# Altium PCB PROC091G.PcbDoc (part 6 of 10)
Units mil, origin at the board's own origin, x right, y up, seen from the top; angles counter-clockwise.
Board outline 4538.11 x 994.94 mil, 8 copper layers (Top Layer, GND1, Sig1, PWR1, PWR2, Sig2, GND2, Bottom Layer), stack 59.155 mil thick; 446 components, 329 nets, 5050 pads, 868 vias.
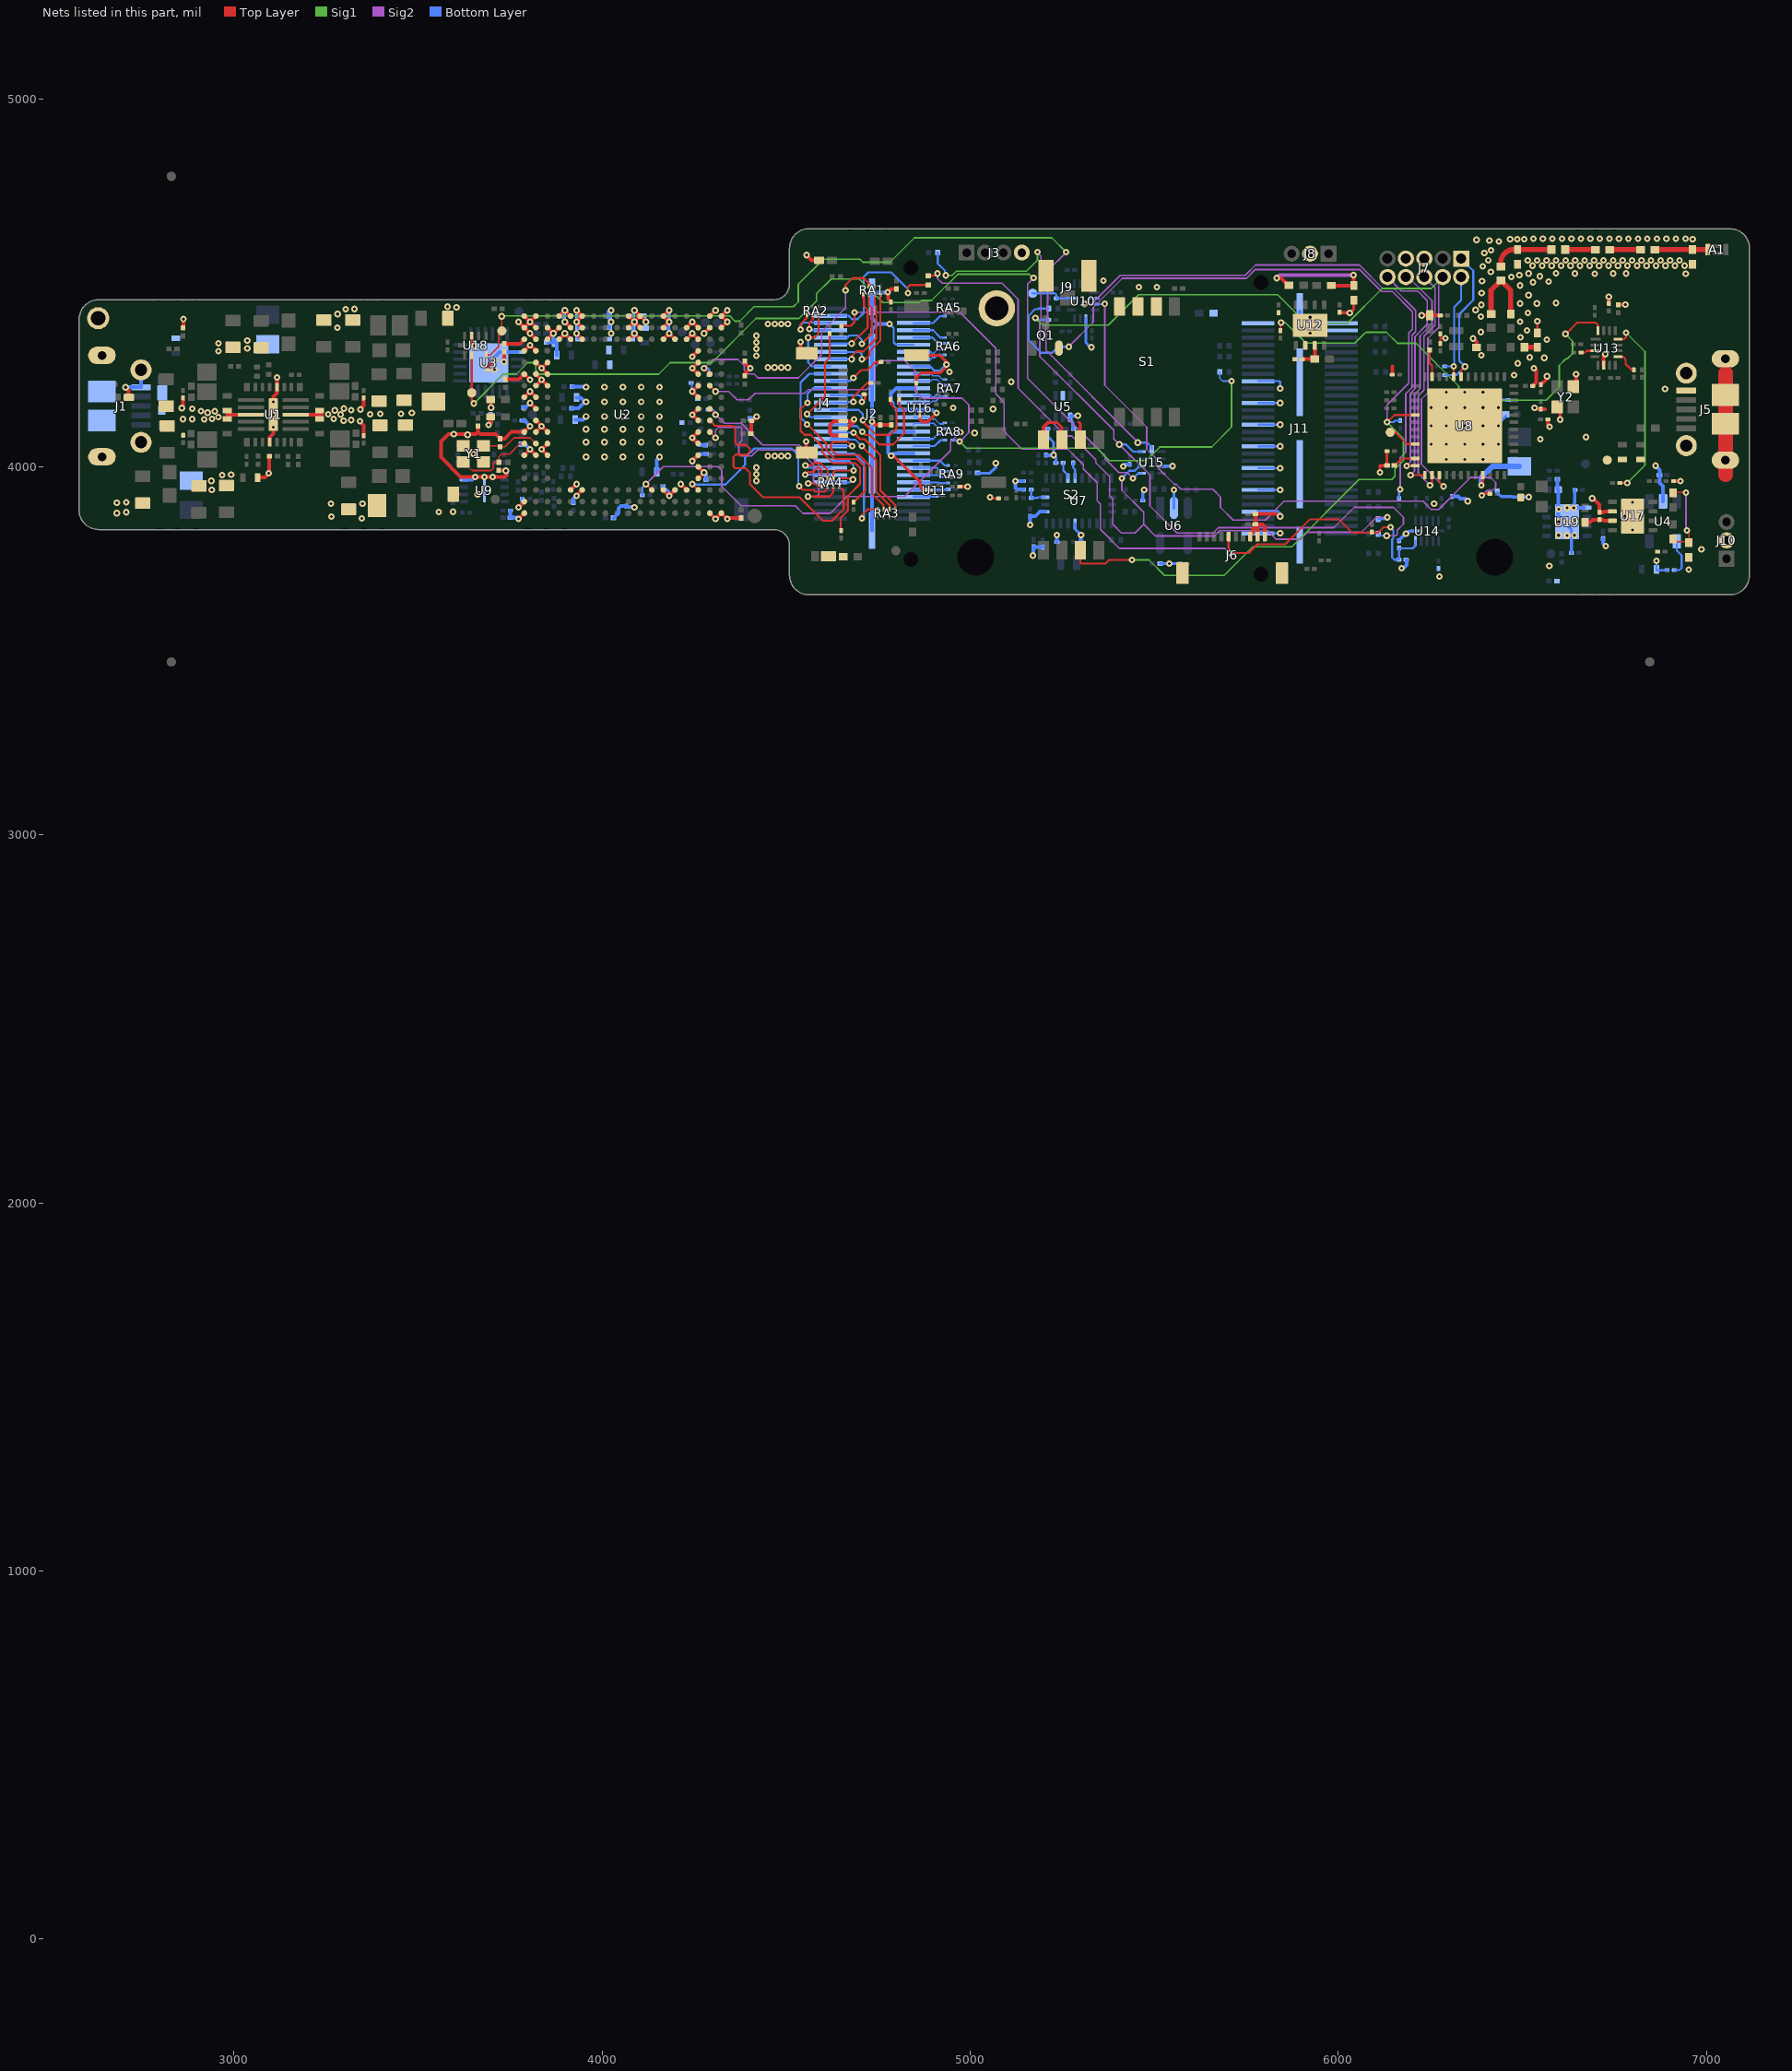
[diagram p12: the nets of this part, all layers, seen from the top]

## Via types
v1: diameter 18, hole 8, Top Layer to Bottom Layer, tented both sides, 832 vias
v2: diameter 19.68, hole 7.87, Top Layer to Bottom Layer, tented both sides, 34 vias
v3: diameter 17, hole 7.87, Top Layer to Bottom Layer, tented both sides, 1 vias
v4: diameter 17, hole 8, Top Layer to Bottom Layer, tented both sides, 1 vias

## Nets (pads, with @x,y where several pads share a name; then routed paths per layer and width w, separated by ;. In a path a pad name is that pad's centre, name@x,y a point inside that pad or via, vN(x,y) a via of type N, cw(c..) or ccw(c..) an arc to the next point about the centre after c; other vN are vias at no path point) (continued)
AR_SYNC_IN: R157.1 RA8.8 U2.U12 | length 1975
  Top Layer w5.5: U2.U12@4292.7,4220.35 v1(4308.45,4204.6)
  Sig1 w4.2: v1(4971.61,4068.25) 4989.78,4050.08 5344.37,4050.08 5377.44,4017.01 5478.18,4017.01 5514.94,4053.77 5656.33,4053.77 5710.24,4107.68 v1(5710.24,4232.45)
  Sig2 w4.2: v1(4308.45,4204.6) 4344.14,4204.6 4367.21,4181.54 4397.56,4181.54 4415.59,4199.56 4550.34,4199.56 4560.42,4209.65 4718.86,4209.65 4741.87,4232.66 4741.87,4271.44 4759.12,4288.69 4822.4,4288.69 4850.94,4260.15 4850.94,4204.65 4869.22,4186.37 4978,4186.37 4996.41,4167.96 4996.41,4093.05 v1(4971.61,4068.25)
  Bottom Layer w4.2: R157.1@5678.13,4257.72 5678.13,4240.18 5685.85,4232.45 v1(5710.24,4232.45)
  Bottom Layer w5.5: RA8.8@4952.69,4072.25 4967.61,4072.25 v1(4971.61,4068.25)
AR_SYNC_OUT_SOP1: R84.1 RA8.7 U2.M3 | length 1135.8
  Top Layer w5.5: v1(4119.47,3952.63) U2.M3@4135.22,3936.89
  Sig2 w4.2: v1(4119.47,3952.63) 4167.16,4000.33 4313.89,4000.33 4325.09,3989.12 4325.09,3946.41 4377.92,3893.59 4525.16,3893.59 4545.46,3873.29 4620.23,3873.29 4665.56,3918.63 4821.98,3918.63 4947.18,4043.83 4947.18,4067.33 v1(4973.31,4093.46)
  Bottom Layer w5.5: R84.1@4109.37,3922.4 4109.37,3942.53 v1(4119.47,3952.63) ; RA8.7@4952.69,4088 4967.85,4088 v1(4973.31,4093.46)
AR_TCK: RA4.2 U2.T3 | length 552.9
  Top Layer w5.5: v1(4245.46,3952.63) U2.T3@4261.2,3936.89 ; v1@4532.81,3949.39 v1(4535.35,3946.85) 4544.91,3937.29 4573.76,3937.29 4579.07,3931.99 4604.64,3931.99 4612.69,3940.04 RA4.2@4612.69,3946.67
  Bottom Layer w5.5: v1(4245.46,3952.63) 4246.46,3951.63 4335.33,3951.63 4388.35,4004.65 4388.35,4024.15 4414.2,4050 4514.75,4050 4532.92,4031.83 4532.92,3949.29 v1(4535.35,3946.85)
AR_TDI: RA4.4 U2.U9 | length 705.9
  Top Layer w5.5: U2.U9@4292.7,4125.86 4307.32,4111.24 4353.47,4111.24 4361.57,4103.14 4361.57,4065.53 4367.7,4059.39 4391,4059.39 4401.46,4048.93 4401.46,4040.6 4393.56,4032.7 4363.3,4032.7 4357.05,4026.45 4357.05,4000.45 4361.5,3996 4389.59,3996 4401.46,3984.13 4401.46,3952.48 4437.05,3916.9 4536.15,3916.9 4599.89,3853.17 4624.33,3853.17 4656.39,3885.22 4656.39,3934.47 RA4.4@4644.19,3946.67
AR_TDO_SOP0: R83.1 RA4.3 U2.U10 | length 591.7
  Top Layer w5.5: U2.U10@4292.7,4157.36 v1(4308.45,4141.61) ; v1(4559.05,3919.14) 4617.44,3919.14 4628.44,3930.13 RA4.3@4628.44,3946.67
  Sig2 w4.2: v1(4308.45,4141.61) 4332.17,4117.89 4378.11,4117.89 4436.42,4059.59 4535.55,4059.59 4588.41,4006.72 4588.41,3924.98 4582.57,3919.14 v1(4559.05,3919.14)
  Bottom Layer w4.2: R83.1@4288.32,4155.3 4301.27,4155.3 4308.45,4148.13 v1(4308.45,4141.61)
AR_TMS: RA4.1 U2.U8 | length 524.5
  Top Layer w5.5: U2.U8@4292.7,4094.37 v1(4308.45,4078.62) ; v1(4559.88,3955.04) 4577.77,3955.04 4586.24,3946.57 4596.85,3946.57 RA4.1@4596.94,3946.67
  Sig2 w4.2: v1(4308.45,4078.62) 4308.45,4099.58 4316.49,4107.62 4376.5,4107.62 4379.39,4104.74 4379.39,4070.75 ; 4379.05,4070.75 4371.62,4063.31 4371.62,4034.19 4376.26,4029.55 4406,4029.55 4422.02,4045.57 4533.98,4045.57 4574.54,4005 4574.54,3957.33 4572.26,3955.04 v1(4559.88,3955.04)
AR_VBGAP: C69.1 U2.A16 | length 59.2
  Top Layer w10: C69.1@3734.67,4334 3776.43,4334 U2.A16@3788.76,4346.33
AR_WARMRST: R23.1 RA1.3 U2.U13 | length 737.3
  Top Layer w5.5: v1(4276.95,4267.59) U2.U13@4292.7,4251.85 ; v1(4661.37,4479.46) 4661.37,4494.02 4680.05,4512.7 4710.79,4512.7 4725.3,4498.19 RA1.3@4725.3,4490.32
  Sig2 w4.2: v1(4276.95,4267.59) 4301,4291.65 4368.95,4291.65 4386.74,4273.85 4386.74,4261.99 4396.6,4252.14 4413.04,4252.14 4423.61,4241.56 4532.94,4241.56 4596.17,4304.79 4596.17,4366.53 4661.37,4431.73 v1(4661.37,4479.46)
  Bottom Layer w5.5: v1(4276.95,4267.59) 4287.51,4267.59 4290.72,4264.38 R23.1@4290.72,4249.29
AR_XTAL_N: C71.2 U2.B7 Y1.3 | length 159.9
  Top Layer w4: Y1.3@3678.09,4056.69 3720.4,4056.69 C71.2@3722.86,4054.22 3736.32,4054.22 3760.84,4078.74 3804.39,4078.74 U2.B7@3820.26,4062.87
AR_XTAL_P: C14.2 R109.1 U2.A7 Y1.1 | length 222.5
  Top Layer w4: Y1.1@3622.98,4013.38 3646.72,3989.63 3697.93,3989.63 3704.65,3996.36 3704.65,4009.85 3707.19,4012.38 C14.2@3719.34,4012.38 3719.34,4027.12 3726.72,4034.49 3748.57,4034.49 3776.95,4062.87 U2.A7@3788.76,4062.87
BOOTN: R80.2 R96.1 U7.4 | length 61.7
  Bottom Layer w5.5: R96.1@5166,3938 R80.2@5166,3915 5182.2,3915 5184.27,3917.06 U7.4@5203.84,3917.06
BREAK_RS232RX: TP19.1 U15.6 U18.7 | length 2614
  Top Layer w5.5: U18.7@3645.95,4303.01 TP19.1@3645.95,4200.94 3645.95,4177.64 v1(3651.7,4171.89)
  Sig1 w4.2: v1(3651.7,4171.89) 3651.8,4171.89 3731.31,4251.4 3766.68,4251.4 3798.17,4282.89 3810.85,4282.89 3819.81,4273.93 3819.81,4262.15 3830.57,4251.4 4153.63,4251.4 4185.13,4282.89 4297.89,4282.89 4417.91,4402.91 4534.91,4402.91 4582.46,4450.46 4582.46,4470.35 4622.27,4510.16 4699.37,4510.16 4763.04,4446.48 4862.39,4446.48 4867.61,4451.7 4894.97,4451.7 4966.18,4522.91 5161.16,4522.91 5171.18,4512.9 v1(5172.08,4512.9)
  Sig2 w4.2: v1(5172.08,4512.9) 5155.67,4496.49 5155.67,4240 5366.25,4029.42 5366.25,4021.65 5403.71,3984.18 5426.56,3984.18 v1(5442.13,3968.62)
  Bottom Layer w5.5: v1(5442.13,3968.62) 5448.38,3974.87 5449.25,3974.87 5456.39,3982 U15.6@5466.7,3982
BREAK_RS232TX: TP18.1 U15.10 U18.9 | length 2507
  Top Layer w4.2: U18.9@3685.32,4303.01 3695.92,4303.01 3718.72,4325.81 3718.72,4360.18 TP18.1@3727.56,4369.01 v1@3727.56,4409.77
  Sig1 w4.2: v1@3727.56,4409.77 4347.13,4409.77 4361.3,4395.61 4373.97,4395.61 4413.02,4434.66 4519.99,4434.66 4533.24,4447.91 4533.24,4495.82 4601.12,4563.7 4700.52,4563.7 4708.47,4555.75 4782.14,4555.75 4848.39,4622 5221.85,4622 v1(5260.87,4582.98)
  Sig2 w4.2: v1(5260.87,4582.98) 5210.52,4532.63 5210.52,4391.71 5205.79,4386.98 5205.79,4316.68 5455.37,4067.1 v1(5455.37,4065.46)
  Bottom Layer w5.5: v1(5455.37,4065.46) 5480.68,4065.46 5493.27,4052.87 U15.10@5493.27,4046.96
  other v1: 3727.56,4408.57
"BT ENABLE": R30.1 R110.1 S2.3 U8.17 | length 3008.7
  Top Layer w5.5: S2.3@5299.37,3783.46 S2.3@5299.37,3773.46 5299.26,3773.36 5299.26,3739.99 5302.49,3736.76 5367.55,3736.76 5377.49,3746.7 v1(5439.63,3746.7) ; v1(6132.81,4121) 6152.45,4140.64 U8.17@6209.52,4140.64
  Sig1 w4.2: v1(5439.63,3746.7) 5485.98,3746.7 5527.67,3705.01 5689.9,3705.01 5767.77,3782.88 5874.22,3782.88 6056.33,3965 6145.02,3965 6153.99,3973.96 6153.99,3993.66 6177.18,4016.86 6177.18,4076.63 v1(6132.81,4121)
  Sig2 w4.2: v1(5267.72,4325.88) 5334.59,4392.74 5334.59,4433.01 5413.38,4511.8 5750.7,4511.8 5774.76,4535.86 6057.61,4535.86 6117.46,4476.01 6147.19,4476.01 6201.81,4421.39 6201.81,4373.78 6191.46,4363.43 6191.46,4227 6132.81,4168.36 v1(6132.81,4121)
  Bottom Layer w5.5: R30.1@5213.2,4430 5186.09,4430 5184.12,4428.03 5176.34,4428.03 5159.47,4411.15 5159.47,4343.39 5193.14,4309.72 5222.77,4309.72 5238.93,4325.88 v1(5267.72,4325.88) ; v1(6132.81,4121) 6150.4,4121 6154.66,4125.26 R110.1@6168.27,4125.26
BT_RST: R91.2 U10.3 | length 1681.3
  Top Layer w5.5: v1(6390.18,3921.94) 6394.7,3926.46 R91.2@6411.94,3926.46
  Sig2 w4.2: v1(5365.82,4442.61) 5365.82,4221.37 5479.87,4107.32 5479.87,4047.4 5505.03,4022.24 5505.03,4001.91 5554.74,3952.2 5559.87,3952.2 5573.17,3938.9 5659.1,3938.9 5679.91,3918.1 5679.91,3889.52 5714.11,3855.32 5801.95,3855.32 5852.96,3906.32 6230.06,3906.32 6252.22,3884.16 6272.56,3884.16 6359.46,3971.06 6413.59,3971.06 6427.58,3957.07 6427.58,3944.39 6417.67,3934.49 6402.73,3934.49 v1(6390.18,3921.94)
  Bottom Layer w5.5: U10.3@5338.3,4441.85 5365.07,4441.85 v1(5365.82,4442.61)
BT_UART_RX: J7.1 R90.2 U8.7 | length 426
  Top Layer w5.5: U8.7@6333.54,4244.97 6333.58,4245 6333.58,4261.53 v1(6344.18,4272.14)
  Bottom Layer w5.5: R90.2@6289,4249 6321.04,4249 v1(6344.18,4272.14) 6328.44,4287.88 6328.44,4414.44 6367,4453 6367,4532.4 J7.1@6333.84,4565.56
BT_UART_TX: J7.2 R102.2 U8.8 | length 303.7
  Top Layer w5.5: U8.8@6313.85,4244.97 v1(6313.85,4272.45)
  Bottom Layer w5.5: R102.2@6289,4272.45 v1(6313.85,4272.45) 6314.96,4273.56 6314.96,4433.35 6333.84,4452.23 J7.2@6333.84,4515.56
CAN1_FD_RX: R127.2 U13.3 | length 39.7
  Top Layer w5.5: R127.2@6659.81,4310 6669.93,4310 6674.81,4314.88 U13.3@6697.44,4314.88
CAN1_FD_TX: R123.2 U13.16 | length 1207.8
  Top Layer w5.5: R123.2@5843.14,4369.72 5843.14,4390.03 v1(5844.47,4391.36) ; v1(6617,4361) 6619,4361 6650,4392 6697.81,4392 6705.32,4384.5 U13.16@6705.32,4370
  Sig1 w4.2: v1(5844.47,4391.36) 5856.6,4391.36 5912.32,4335.65 6045.15,4335.65 6067.63,4358.12 6067.73,4358.12 6075.08,4365.48 6130.85,4365.48 6160.8,4335.52 6210.7,4335.52 6327.24,4218.99 6327.24,4195.96 6342.84,4180.35 6564.35,4180.35 6600.31,4216.31 6600.31,4275.14 6618.29,4293.11 6622.56,4293.11 6636.76,4307.31 6636.76,4341.24 v1(6617,4361)
CAN2_FD_RX: R120.2 U13.9 | length 65
  Top Layer w5.5: U13.9@6760.43,4299.13 6773.81,4299.13 6780.81,4292.13 6780.81,4279.1 6796.91,4263 R120.2@6802.81,4263
CAN2_FD_TX: R116.2 U13.12 | length 505
  Top Layer w4: R116.2@6764.81,3956 v1(6784.78,3956)
  Top Layer w5.5: U13.12@6760.43,4346.38 6776.09,4346.38 6781.81,4352.1 v1(6781.81,4364)
  Sig1 w4.2: v1(6781.81,4364) 6833.19,4312.62 6833.19,4004.29 6784.9,3956 v1(6784.78,3956)
CLKSEL0: R82.2 U7.10 | length 43.9
  Bottom Layer w5.5: R82.2@5279.72,4010.48 5279.72,3997.37 5285.04,3992.06 U7.10@5285.04,3968.74
CONN_AR_RS232RX: R14.2 R188.2 U15.7 | length 2067.2
  Top Layer w5.5: R14.2@4886,4519.05 v1@4906.72,4519.05
  Sig2 w4.2: v1(4911,4525) 4911,4511.37 4923.96,4498.41 5086.69,4498.41 5130.47,4454.63 5130.47,4212.92 5259.77,4083.62 5276.41,4083.62 5341.05,4018.98 5341.05,4011.21 5378.87,3973.39 5378.87,3920.96 5387.27,3912.56 5387.27,3843.8 5410.85,3820.21 5448.03,3820.21 5471.33,3843.51 ; v1(5412.13,3968.62) 5412.13,3935.85 5471.33,3876.64 5471.33,3843.51 ; v1(6132.96,3862.86) 6104.11,3862.86 6063.07,3821.83 5916.36,3821.83 5897.84,3803.31 5831.23,3803.31 5808.57,3825.97 5677.97,3825.97 5663.79,3811.79 5503.06,3811.79 5471.33,3843.51
  Bottom Layer w5.5: v1(5412.13,3968.62) 5432.38,3988.87 5447,3988.87 5459.81,4001.69 U15.7@5466.7,4001.69 ; R188.2@6108.34,3857.41 6127.51,3857.41 v1(6132.96,3862.86)
CONN_AR_RS232TX: R12.2 R189.2 U15.9 | length 2116.3
  Sig1 w4.2: v1(4934,4520) 4951.39,4520 4962.7,4531.31 5153.03,4531.31 5182.91,4561.2 v1(5182.91,4583.44)
  Sig2 w4.2: v1(5182.91,4583.44) 5182.91,4581.72 5192.52,4572.11 5192.52,4397.46 5188.99,4393.94 5188.99,4299.96 5390.07,4098.88 5390.07,4075.76 v1(5405.37,4060.46) 5488.23,3977.6 5488.23,3893.35 5561.39,3820.19 5660.09,3820.19 5674.27,3834.37 5988.08,3834.37 6043.23,3889.52 6150.46,3889.52 6177.08,3862.9 6177.08,3844.62 6160.45,3827.99 6160.45,3816.72 6156.2,3812.47 v1(6131.43,3812.47)
  Bottom Layer w4.2: R189.2@6108.34,3817.56 6113.43,3812.47 v1(6131.43,3812.47)
  Bottom Layer w5.5: R12.2@4911.77,4582.07 4911.77,4552 4931.61,4532.16 4931.61,4522.39 v1(4934,4520) ; v1(5405.37,4060.46) 5423.46,4060.46 5442.87,4041.06 U15.9@5466.7,4041.06
DCDC_SW: L7.1 U8.33 | length 165.6
  Top Layer w8: v1(6388.68,3950) 6392.59,3953.91 U8.33@6392.59,3977.25
  Bottom Layer w15: v1(6388.68,3950) 6388.68,3971.1 6418.41,4000.83 L7.1@6491.96,4000.83
DIO6_GLED: R17.1 U8.11 | length 74.9
  Top Layer w5.5: R17.1@6248.18,4317.15 6248.18,4281.63 6254.8,4275.01 U8.11@6254.8,4244.97
DISP: R168.2 U10.2 | length 1558.3
  Sig2 w4.2: v1(5310.71,4442.29) 5329.63,4442.29 5407.55,4520.2 5747.22,4520.2 5775.15,4548.13 6057.22,4548.13 6120.94,4484.41 6150.67,4484.41 6210.21,4424.87 6210.21,4367.53 6199.86,4357.18 6199.86,4215.17 6183.57,4198.88 6183.57,4040.24 6168.18,4024.86 v1(6168.18,3938.46)
  Bottom Layer w5.5: v1(5310.71,4442.29) 5311.06,4442.29 5326.37,4457.6 U10.2@5338.3,4457.6 ; R168.2@6165.24,3913.58 6165.24,3935.52 v1(6168.18,3938.46)
DISP_T: C114.2 J6.5 R180.2 R181.1 R182.1 U14.5 | length 2291.6
  Top Layer w5.5: R182.1@4650.14,4382.85 4675.87,4382.85 4685.68,4392.66 v1(4685.68,4419.55) ; J6.5@5702.06,3810.06 5702.06,3768.19 v1(5704.87,3765.38) 5756.17,3765.38 5780.3,3789.51 5856.05,3789.51 5923.83,3857.29 6001.48,3857.29 6037.76,3821 6108.26,3821 6122.64,3835.38 v1(6141.68,3835.38)
  Sig2 w4.2: v1(4685.68,4419.55) 4971.97,4419.55 5069.53,4321.99 5069.53,4197.82 5092.36,4174.99 5092.36,4096.01 5139.98,4048.39 5264.12,4048.39 5307.45,4005.07 5307.45,3994.11 5345.27,3956.29 5345.27,3907.04 5353.67,3898.64 5353.67,3829.88 5405.36,3778.19 5692.07,3778.19 v1(5704.87,3765.38)
  Bottom Layer w5.5: v1(6141.68,3835.38) 6149.18,3827.88 6149.18,3805.12 6146.64,3802.57 6146.64,3753.22 6152.51,3747.34 6163.54,3747.34 6165.19,3748.99 6165.19,3778.13 6201.92,3778.13 6209.55,3785.75 U14.5@6209.55,3797.8 U14.5@6209.55,3799.77
GND: C1.1 C2.1 C3.1 C4.2 C5.2 C6.1 C7.2 C8.2 C9.1 C10.1 C11.2 C12.1 C13.1 C14.1 C15.2 C16.2 C17.2 C18.2 C19.2 C20.2 C21.1 C23.2 C24.2 C25.2 C26.2 C27.2 C28.2 C29.2 C30.2 C31.2 C32.2 C33.2 C34.2 C35.2 C36.2 C37.2 C38.2 C39.2 C40.2 C41.2 C42.1 C43.1 C44.2 C45.2 C46.2 C47.2 C50.2 C51.2 C52.2 C53.2 C55.2 C56.2 C57.2 C58.2 C59.2 C60.2 C61.2 C62.2 C63.2 C64.2 C65.2 C66.2 C67.2 C68.2 C69.2 C70.2 C71.1 C72.1 C73.2 C74.2 C75.2 C76.2 C78.2 C79.2 C80.2 C81.2 C82.2 C83.2 C84.2 C85.2 C86.2 C87.2 C88.2 C89.2 C90.2 C91.2 C92.2 C94.2 C95.2 C96.2 C97.2 C98.2 C100.2 C101.2 C102.2 C103.2 C104.2 C105.1 C106.1 C107.2 C108.1 C109.1 C110.1 C111.2 C112.2 C113.2 C114.1 C115.2 C116.2 C117.2 C118.2 C119.2 C120.2 C121.2 C122.2 C123.2 C124.2 C125.2 C126.2 C127.2 C128.2 C129.2 C130.2 C131.2 C132.2 C133.2 C134.2 C135.2 C136.2 C137.2 C138.2 C139.2 C140.2 C141.2 J1.5 J1.6 J1.7 J1.8 J1.9 J1.10 J1.11 J2.20 J2.26 J2.32 J2.38 J2.44 J2.50 J2.MP1 J2.MP2 J2.MP3 J2.MP4 J3.4 J4.8 J4.9 J4.10 J4.11 J4.12 J5.5 J5.6 J5.7 J5.8 J5.9 J5.10 J5.11 J6.8 J6.9 J6.10 J6.11 J6.12 J7.5 J7.7 J8.2 J9.2@5206.05,4518.36 J9.3@5322.19,4518.36 J10.2 J11.18 J11.24 J11.30 J11.36 J11.42 J11.48 J11.54 J11.60 J11.MP1 J11.MP2 J11.MP3 J11.MP4 LD1.2 LD2.2 LD6.2 Q1.2 R3.2 R15.1 R24.1 R29.1 R37.1 R42.2 R52.1 R65.1 R69.1 R73.1 R92.2 R93.2 R96.2 R98.2 R122.2 R125.1 R134.2 R141.2 R158.1 R170.1 R172.1 R180.1 S1.6 S1.7 S1.8 S2.6 S2.7 S2.8 SW2.2 TP12.1 TP15.1 TP20.1 U1.4 U1.11 U1.17 U1.24 U1.27 U2.A1 U2.A2 U2.A6 U2.A8 U2.A11 U2.A13 U2.A15 U2.A17 U2.A18 U2.B6 U2.B8 U2.B9 U2.B10 U2.B11 U2.B12 U2.B13 U2.B14 U2.B15 U2.B16 U2.B17 U2.B18 U2.C6 U2.C7 U2.C8 U2.C12 U2.C13 U2.C14 U2.C16 U2.C17 U2.D16 U2.D17 U2.D18 U2.E3 U2.E16 U2.E17 U2.E18 U2.F3 U2.F16 U2.F17 U2.F18 U2.K16 U2.K17 U2.K18 U2.L16 U2.L17 U2.L18 U2.N3 U2.N16 U2.N17 U2.N18 U2.P3 U2.P16 U2.R3 U2.R16 U2.R17 U2.T4 U2.T5 U2.T6 U2.T7 U2.T8 U2.T9 U2.T10 U2.T11 U2.T12 U2.T13 U2.T14 U2.T15 U2.T16 U2.T17 U2.U1 U2.U17 U2.U18 U2.V1 U2.V17 U2.V18 U3.2 U3.25 U4.2 U5.2 U5.4 U6.2 U7.2 U7.25 U8.49 U9.4 U9.9 U10.6 U10.16 U11.2 U12.2 U12.9@5923.44,4384.46 U13.6 U14.6 U15.3 U16.2 U17.2 U17.9@6799.78,3866 U18.3 U19.5 U19.9@6621.18,3850.46 Y1.2 Y1.4 Y2.2 Y2.4 | length 10400.1
  Top Layer w5.5: v1(5054,3917) 5056.96,3914.04 R125.1@5077.13,3914.04 ; C20.2@6277.6,4334.83 6277.6,4349 ; C19.2@6277.6,4361.03 6277.6,4349 ; v1(6290.81,4348.8) 6290.61,4349 6277.6,4349 ; C21.1@6540.73,4363.78 v1(6540.73,4395.08) ; v1@6734.81,4462 v1(6735.03,4461.78) ; v1(6780.09,4440.28) v1@6780.81,4441
  Top Layer w8: v1(4785.33,4029.82) 4791.76,4029.82 4865.14,3956.44 4865.14,3943.16 4872.16,3936.15 4886.95,3936.15 U11.2@4886.95,3935.72 ; C72.1@4853.37,4227.49 4853.37,4242.21 4866.4,4255.24 4918.89,4255.24 4935.65,4272 v1(4935.65,4278) 4935.65,4284.18 4916.82,4303.01 SW2.2@4854.16,4303.01 ; U16.2@4863.37,4143.71 4863.37,4127.78 4869.25,4121.9 4884.53,4121.9 v1(4908.49,4145.87) ; 5211.17,4119.83 5236.79,4119.83 5249.16,4107.46 5249.16,4073.68 S2.7@5249.37,4073.46 ; 5294.73,4121.32 5299.37,4116.68 S2.6@5299.37,4073.46 ; C105.1@6003.64,4419.31 6004.47,4418.48 6030.47,4418.48 v1(6031.3,4417.65) 6031.3,4417.89 6042.24,4428.83 6042.24,4452.55 C106.1@6042.33,4452.64 ; v1(6112.93,3984.42) 6112.93,4002.42 6113.45,4002.94 6131.94,4002.94 C24.2@6132.46,4003.46 6132.31,4003.61 6132.31,4042.07 C26.2@6132.17,4042.21 ; v1(6602.58,4128.23) 6602.73,4128.38 Y2.2@6602.73,4162.29 ; v1@6670.77,4082.88 v1(6673.18,4080.46) v1@6674.18,4081.46
  Top Layer w10: v1(2705.44,4215.83) 2714.14,4207.14 2714.14,4188.74 LD1.2@2714.37,4188.5 ; v1(2858.16,4159.24) 2858.16,4161.4 2861.78,4165.02 C31.2@2861.78,4187.39 ; R52.1@2861.97,4377.4 2862.18,4377.61 2862.18,4401.08 v1(2862.39,4401.29) ; v1(2919.37,4128.71) 2919.37,4126.51 v1@2920.67,4125.21 ; v1@2920.96,4124.92 v1@2920.67,4125.21 ; v1@2921.67,4125.21 v1@2920.67,4125.21 ; 2981.1,4142.5 2981.99,4141.61 U1.11@3046.37,4141.61 ; C1.1@3064.3,3970.8 3084.39,3970.8 v1@3093.43,3979.84 ; v1(3094.18,3981.91) 3095.98,3983.71 C30.2@3095.98,4029 ; U1.17@3097.16,4066.81 3097.16,4079.6 3106.96,4089.41 3106.96,4097.36 ; v2(3107,4141.61) v2(3107,4175.86) 3107,4189.72 3116.84,4199.56 U1.4@3116.84,4216.41 3116.84,4242.45 v1(3117,4242.61) ; U1.24@3167.63,4141.61 3238.85,4141.61 3238.92,4141.67 ; v1(3342.61,4123.89) 3342.61,4121.72 3352.48,4111.85 C34.2@3352.48,4084.05 ; v1(3343.33,4155.49) 3343.33,4157.66 3351.98,4166.31 3351.98,4187.22 C33.2@3352.15,4187.39 ; C138.2@3586.42,3926.29 C138.2@3608.83,3926.29 ; Y1.4@3622.98,4056.69 3628.88,4056.69 v4(3650.54,4035.03) 3672.19,4013.38 Y1.2@3678.09,4013.38 ; Y1.4@3623.17,4054.18 Y1.4@3629.39,4054.18 ; U18.3@3645.95,4354.59 3645.95,4336.82 v1(3653.37,4329.4) ; R15.1@3663,4110.46 3663,4095 ; Y1.2@3672.7,4010.87 Y1.2@3678.28,4010.87 ; C126.2@3690.95,4262.91 3690.95,4273.3 v1(3707.55,4289.9) ; v1(3691.74,4113.6) 3697.82,4119.68 C89.2@3697.82,4135.45 ; C90.2@3697.69,4182.85 3697.69,4160.66 v1@3697.82,4160.53 ; C14.1@3724.34,3990.34 3725.45,3989.23 v1(3738.48,3989.23) 3741.28,3989.23 3741.28,3978.28 3735.46,3972.46 v1(3703.21,3972.46) v1(3655,3972.46) 3615.61,3972.46 3562.24,4025.83 3562.24,4068.17 3582.87,4088.8 v1(3596.96,4088.8) 3656.8,4088.8 3663,4095 ; v1(3733.44,4284.91) 3734.67,4286.14 C69.2@3734.67,4311.95 ; C63.2@3737.19,4237.51 3774.43,4237.51 U2.A13@3788.76,4251.85 v1(3804.51,4236.1) ; v1(3773.02,3858.15) U2.A1@3788.76,3873.89 ; v1(3773.02,3889.64) U2.A2@3788.76,3905.39 ; v1(3773.02,4393.58) U2.A17@3788.76,4377.83 ; U2.A6@3788.76,4031.37 v1(3804.51,4047.12) U2.B6@3820.26,4031.37 ; U2.A11@3788.76,4188.85 v1(3804.51,4204.6) U2.B11@3820.26,4188.85 ; U2.A15@3788.76,4314.84 v1(3804.51,4330.59) U2.B15@3820.26,4314.84 ; U2.A18@3788.76,4409.33 v1(3804.51,4393.58) ; v1(3804.51,4110.11) U2.A8@3788.76,4094.37 3753.66,4094.37 3735.12,4075.82 3723.31,4075.82 C71.1@3722.86,4076.27 3722.86,4077.06 3710.92,4089 3669,4089 3663,4095 ; v1(3804.51,4173.11) U2.B10@3820.26,4157.36 ; U2.B8@3820.26,4094.37 v1(3836.01,4110.11) ; U2.B9@3820.26,4125.86 v1(3836.01,4110.11) ; U2.B12@3820.26,4220.35 v1(3836.01,4236.1) ; U2.B13@3820.26,4251.85 v1(3836.01,4236.1) ; U2.B14@3820.26,4283.34 v1(3836.01,4267.59) ; U2.B16@3820.26,4346.33 v1(3804.51,4362.08) U2.A17@3788.76,4377.83 ; U2.B17@3820.26,4377.83 v1(3804.51,4393.58) ; U2.B18@3820.26,4409.33 v1(3804.51,4393.58) ; U2.C6@3851.76,4031.37 v1(3836.01,4047.12) U2.C7@3851.76,4062.87 ; U2.C8@3851.76,4094.37 v1(3836.01,4110.11) ; U2.C12@3851.76,4220.35 v1(3836.01,4236.1) ; U2.C13@3851.76,4251.85 v1(3836.01,4267.59) ; U2.C14@3851.76,4283.34 v1(3836.01,4267.59) ; U2.C16@3851.76,4346.33 v1(3867.5,4362.08) ; U2.C17@3851.76,4377.83 v1(3867.5,4362.08) ; U2.D16@3883.25,4346.33 v1(3899,4362.08) U2.E16@3914.75,4346.33 ; U2.D17@3883.25,4377.83 v1(3867.5,4362.08) ; U2.D18@3883.25,4409.33 v1(3899,4425.07) U2.E18@3914.75,4409.33 ; v1(3899,4393.58) U2.E17@3914.75,4377.83 ; U2.E3@3914.75,3936.89 v1(3930.5,3952.63) ; v1(3930.5,3921.14) U2.F3@3946.24,3936.89 ; v1(3930.5,4362.08) U2.F16@3946.24,4346.33 ; v1(3930.5,4425.07) U2.F18@3946.24,4409.33 v1(3930.5,4393.58) U2.F17@3946.24,4377.83 ; U2.K16@4072.23,4346.33 v1(4087.98,4362.08) U2.L16@4103.72,4346.33 ; U2.K17@4072.23,4377.83 v1(4087.98,4393.58) ; U2.K18@4072.23,4409.33 v1(4087.98,4393.58) ; v1(4087.98,4425.07) U2.L18@4103.72,4409.33 ; U2.L17@4103.72,4377.83 v1(4087.98,4393.58) ; v1(4119.47,4393.58) U2.L18@4103.72,4409.33 ; U2.N3@4166.72,3936.89 v1(4182.46,3921.14) U2.P3@4198.21,3936.89 ; U2.N16@4166.72,4346.33 v1(4182.46,4362.08) U2.P16@4198.21,4346.33 ; U2.N17@4166.72,4377.83 v1(4182.46,4393.58) U2.N18@4166.72,4409.33 v1(4182.46,4425.07) ; v1(4213.96,3952.63) U2.R3@4229.71,3936.89 ; U2.R16@4229.71,4346.33 v1(4245.46,4362.08) U2.T16@4261.2,4346.33 ; U2.R17@4229.71,4377.83 v1(4245.46,4393.58) U2.T17@4261.2,4377.83 ; v1(4245.46,4015.63) U2.T6@4261.2,4031.37 ; v1(4245.46,4299.09) U2.T15@4261.2,4314.84 ; U2.T4@4261.2,3968.38 v1(4276.95,3984.13) U2.T5@4261.2,3999.88 ; U2.T7@4261.2,4062.87 v1(4245.46,4078.62) U2.T8@4261.2,4094.37 ; U2.T9@4261.2,4125.86 v1(4245.46,4141.61) U2.T10@4261.2,4157.36 ; U2.T11@4261.2,4188.85 v1(4245.46,4204.6) U2.T12@4261.2,4220.35 ; U2.T13@4261.2,4251.85 v1(4245.46,4267.59) U2.T14@4261.2,4283.34 ; v1(4276.95,4362.08) U2.U17@4292.7,4377.83 ; U2.U1@4292.7,3873.89 v1(4308.45,3858.15) U2.V1@4324.2,3873.89 v1(4339.94,3858.15) 4342.43,3860.63 C60.2@4378.33,3860.63 ; U2.U18@4292.7,4409.33 v1(4308.45,4425.07) ; U2.V17@4324.2,4377.83 v1(4339.94,4393.58) U2.V18@4324.2,4409.33 v1(4339.94,4425.07) ; C96.2@4388.37,4246.78 4388.37,4252.87 v1(4402.94,4267.44) 4388.37,4282.01 C98.2@4388.37,4286.73 ; C102.2@4405.36,4090.24 4405.93,4090.82 C88.2@4405.93,4124.76 4409.76,4124.76 v1@4421,4136 ; v1(4539.65,4338.94) 4539.65,4317.15 4548.63,4308.18 J4.11@4554.03,4308.18 ; J4.12@4554.03,4038.49 v1(4554.03,4068.8) ; v1(4555.92,4574.89) 4569.75,4561.07 LD2.2@4589.4,4561.07 ; J4.10@4655.33,4084.75 4625.21,4084.75 4619.91,4090.06 4619.91,4113.73 4630.3,4124.12 4680.13,4124.12 v1(4684.89,4128.88) 4684.89,4122.77 4666.56,4104.44 J4.9@4655.33,4104.44 ; v1(4733.36,4122.4) 4742.01,4113.75 C16.2@4755.82,4113.75 C15.2@4785.89,4113.75 ; C120.2@4784.37,4447.48 4784.37,4449.27 4777.52,4456.13 4777.52,4472.54 v1(4775.99,4474.07) 4785.12,4483.2 R42.2@4799.25,4483.2 ; C40.2@4971.72,3946.07 4992.98,3946.07 v1(4993.06,3946.15) ; S2.8@5199.37,4073.46 5199.37,4108.03 5211.17,4119.83 ; J6.8@5761.12,3807.06 5761.12,3813.95 5768.6,3821.44 5768.6,3830.62 5772.77,3834.78 5772.77,3842.77 5773.74,3843.74 C116.2@5774.59,3843.74 ; J6.9@5780.8,3807.06 C116.2@5780.8,3839.39 ; J6.10@5800.49,3810.06 5800.49,3837.09 5793.83,3843.74 5775.3,3843.74 5774.59,3844.45 C115.2@5774.59,3872.2 5833.16,3872.2 5840.17,3865.19 v1(5842.34,3865.19) ; C25.2@6146.94,4250.28 6146.94,4272.45 ; v1(6226.68,4411.08) LD6.2@6248.18,4411.08 C37.2@6277.18,4411.08 ; v1(6366.4,4348.67) 6375.72,4339.35 C23.2@6375.72,4324.42 ; C36.2@6528.26,4219.38 6537.19,4228.31 6537.19,4262.62 v1(6531.81,4268) ; 6543.91,4156.74 C18.2@6550.62,4156.74 6561.38,4156.74 ; C17.2@6550.62,4222.96 6567.18,4239.52 v1(6567.18,4245.75) ; C27.2@6569.19,4128.46 6569.19,4113.48 v1(6574.19,4108.48) ; Y2.4@6646.03,4217.41 6646.11,4217.48 6646.11,4251.39 v1(6646.18,4251.46) ; v1(6689.81,3914) 6693.4,3914 6709.78,3897.62 C108.1@6709.78,3876.02 6719.78,3876 6722.58,3878.8 U17.2@6744.66,3878.8 ; U13.6@6721.06,4275.51 v1@6721.06,4299.75 ; C107.2@6735.03,4443.23 v1(6735.03,4461.78) ; R141.2@6760.03,4440.28 v1(6780.09,4440.28) ; R134.2@6910.82,3961 v1(6929.78,3961) ; v1@6986.5,3776.31 v1(6986.81,3776) ; U2.A17@3788.76,4377.83 v1(3804.51,4393.58) ; v1(4087.98,4393.58) U2.L18@4103.72,4409.33 ; v1@6721.06,4299.75 6721.06,4304.25 6720.81,4304 6720.81,4300 v1@6721.06,4299.75
  Top Layer w40: 7051.81,3978.57 J5.6@7051.81,4017.94 J5.7@7051.81,4116.36 J5.8@7051.81,4195.1 7051.81,4254.16
  Bottom Layer w5.5: v1(3930.5,4362.08) 3932.89,4359.69 3932.89,4349.72 C74.2@3936.37,4346.23 ; C130.2@4241.68,4228 4243.57,4226.11 4243.57,4206.49 v1(4245.46,4204.6) 4257.65,4192.4 4257.65,4187.6 C61.2@4259.95,4185.3 ; J11.60@5782.32,3819.07 v1@5840.84,3819.07 ; J11.48@5782.32,3937.18 v1@5840.84,3937.18 ; J11.42@5782.32,3996.23 v1@5840.84,3996.23 ; J11.36@5782.32,4055.29 v1@5840.84,4055.29 ; J11.30@5782.32,4114.34 v1@5840.84,4114.34 ; J11.24@5782.32,4173.4 v1@5840.84,4173.4 ; J11.18@5782.32,4232.45 5840.84,4232.45 5842.34,4230.95 v1(5842.34,4212.77) ; v1(6864.78,3744.15) C7.2@6864.78,3720.79 6864.78,3718.79 6895.97,3718.79 C8.2@6896.18,3719.01
  Bottom Layer w6: v1(4780.88,4387.88) 4792.16,4376.6 4792.16,4337.77 4798.42,4331.51 J2.50@4846.16,4331.51 ; 4785.32,4181.08 4792.37,4174.03 4792.37,4164.78 4800.11,4157.04 4800.11,4154.34 ; v1(6184.15,3818.17) 6184.15,3819.17 6190.34,3825.36 U14.6@6209.55,3825.36
  Bottom Layer w7: J2.44@4846.16,4272.63 4891.24,4272.63 4903.66,4260.22
  Bottom Layer w8: 4903.66,4260.22 4918.25,4260.22 4935.65,4277.62 v1(4935.65,4278) ; R37.1@5019.38,3982.46 5053.74,3982.46 5069.37,3998.09 v1(5069.37,4009.96) ; C6.1@5211,4103.02 5211,4081.73 5226.66,4066.07 v1(5226.66,4031.52) 5232.92,4025.26 C13.1@5232.92,4010.48 ; C125.2@5280.85,4102.9 5280.11,4102.9 5278.94,4104.07 5278.94,4120.07 5271.66,4127.35 U5.4@5271.66,4134.63 5271.66,4136.33 5273.57,4138.23 5291.97,4138.23 5292.43,4138.7 v1(5292.67,4138.7) ; U7.25@5285.04,3845.7 5285.04,3830.71 v1(5301.01,3814.73) ; U10.6@5314.67,4402.48 5314.67,4336.64 5326.44,4324.87 v1(5329.17,4324.87) ; U10.16@5330.42,4496.97 5330.48,4497.04 5330.48,4532.83 5331.66,4534 C117.2@5332.01,4534 C117.2@5333.81,4534 ; v1(5361.92,4505.65) v1@5361.92,4505.89 ; R73.1@5468.87,3908 5468.87,3932.94 v1(5472.93,3937) ; R69.1@5516.13,3737.11 v1(5540.97,3737.11) C12.1@5570.91,3737.11 ; U15.3@5519.85,4001.69 v1(5550.13,4001.69) ; U6.2@5553.54,3887.87 v1@5553.54,3935.9 ; 6432.3,3929.46 6442.63,3919.14 6472.61,3919.14 6474.1,3917.64 v1(6517.93,3917.64) ; v2(6434.91,4111.11) 6434.91,4117.1 C29.2@6455.28,4137.46 ; v2@6435.17,4160.46 v2(6434.91,4160.71) 6434.91,4172.87 6443.3,4181.25 C35.2@6461.34,4181.25 C35.2@6460.17,4180.08 ; U19.9@6611.18,3850.46 6633.26,3828.38 C128.2@6633.26,3766.12 ; U19.9@6630.43,3888.85 6642.17,3900.59 C127.2@6642.17,3936.75
  Bottom Layer w10: v1(2705.44,4215.83) 2705.51,4215.9 2747.59,4215.9 J1.5@2747.66,4215.96 J1.10@2747.66,4263.2 ; U9.4@3625.17,3964.2 3646.74,3964.2 v1(3655,3972.46) ; v1(3691.74,4113.6) 3697.53,4119.4 R65.1@3697.53,4143.04 ; U3.25@3692.64,4282.2 3722.17,4311.72 U3.2@3770.97,4311.72 ; C101.2@3751.01,3881.17 3751.01,3861.79 C100.2@3751.11,3861.69 3769.47,3861.69 v1(3773.02,3858.15) ; v1(3773.02,3889.64) 3783.12,3899.74 R3.2@3783.12,3912.76 ; C97.2@3779.79,4061.22 3790.41,4061.22 v1(3804.51,4047.12) ; C3.1@3782.96,4125.72 3788.9,4125.72 v1(3804.51,4110.11) ; C2.1@3785.88,4160.73 3792.14,4160.73 v1(3804.51,4173.11) ; C67.2@3853,4338.02 3874.98,4338.02 C70.2@3876,4337 ; v1(3867.5,4362.08) 3867.5,4347.58 C70.2@3876,4339.08 ; C73.2@3877,4303 3877,4336 C70.2@3876,4337 ; C68.2@3895.39,4409.24 3895.39,4421.47 v1(3899,4425.07) ; v1(3899,4362.08) C70.2@3876,4339.08 ; C64.2@3918.02,4159 3936,4159 3953.61,4176.61 3942.22,4188 C65.2@3931,4188 ; C66.2@3919.05,4218 3955.09,4218 v1(3956.48,4216.61) ; C95.2@3922.37,3902.78 3922.37,3913.01 v1@3930.78,3921.43 ; C62.2@3927,4128 3947.87,4128 v1(3956.48,4136.61) ; C75.2@3934.43,4409.11 3934.35,4409.02 3934.35,4397.43 v1(3930.5,4393.58) 3936.37,4387.7 C76.2@3936.37,4377.73 ; C84.2@4020.26,4377.83 4020.26,4388.85 v1(4024.98,4393.58) 4020.26,4398.3 C85.2@4020.26,4409.33 ; C87.2@4031,3861.38 4031.79,3861.38 4044.6,3874.19 4044.6,3887.25 4050.46,3893.11 C92.2@4065.74,3893.11 4065.74,3891.31 4065.91,3891.14 4084.26,3891.14 4085.81,3889.59 v1(4087.98,3889.59) ; C80.2@4083.77,4377.76 4083.77,4366.29 v1(4087.98,4362.08) ; C81.2@4084.39,4409.24 4084.39,4397.16 v1(4087.98,4393.58) ; C59.2@4148.3,3985.94 4148.3,4018.43 v1(4156.48,4026.61) ; R170.1@4165.37,3946.46 4182.46,3929.37 v1(4182.46,3921.14) ; C57.2@4177.74,4409.33 4177.74,4398.3 v1(4182.46,4393.58) 4177.39,4388.51 C56.2@4177.39,4378.24 4178.18,4378.24 4179.48,4376.94 4179.48,4376.16 4180.93,4374.7 4180.93,4363.61 v1(4182.46,4362.08) ; C57.2@4179.44,4409.4 4179.66,4409.4 4180.95,4410.7 v1@4180.95,4423.56 ; v1(4245.46,4015.63) 4265,4035.17 C91.2@4282.98,4035.17 ; v1@4245.46,4079.47 v1(4245.46,4078.62) 4265.27,4058.8 C103.2@4280.95,4058.8 ; v1(4276.95,3984.13) 4282.16,3978.92 C94.2@4282.16,3964.68 ; R172.1@4401.11,4131.01 4413.91,4131.01 v1@4421,4138.1 ; v1@4421,4136 v1@4421,4138.1 ; v1@4422.04,4139.14 v1@4421,4138.1 ; J2.MP1@4733.36,3826.98 J2.MP2@4733.36,4019.5 v1(4733.36,4122.4) J2.MP3@4733.36,4269.5 4733.36,4373.14 4748.1,4387.88 ; v1@4775.99,4473.07 4741.12,4473.07 4731.72,4463.66 J2.MP4@4733.36,4462.02 4733.36,4402.63 4748.1,4387.88 ; v1(4780.88,4387.88) 4748.1,4387.88 ; 4785.32,4181.08 4785.32,4198.61 4800.11,4213.4 J2.38@4846.16,4213.4 ; 4800.11,4154.34 J2.32@4846.16,4154.34 4898.01,4154.34 v1@4908.49,4143.87 ; J2.20@4846.16,4036.23 4791.73,4036.23 v1(4785.33,4029.82) 4777.36,4037.79 4777.36,4084.26 4788.39,4095.29 J2.26@4846.16,4095.29 ; v1(5122.82,3961) 5122.82,3943.75 5128.58,3938 R96.2@5144.96,3938 ; v1(5122.82,3961) R98.2@5144.48,3961 ; v1(5162.69,3842.19) C10.1@5162.69,3865.16 5176.2,3865.16 5188.73,3877.69 U7.2@5203.84,3877.69 ; v1@5172.1,3758.57 C11.2@5172.1,3781.54 C9.1@5197.1,3781.54 ; R93.2@5206.3,4031.52 v1(5226.66,4031.52) ; C38.2@5235.57,3795.56 v1(5235.57,3814.73) ; C39.2@5301.01,3795.56 v1(5301.01,3814.73) ; v1(5415.6,4000.98) 5420.98,4006.36 C123.2@5432.91,4006.36 ; J11.54@5782.32,3878.12 5834.41,3878.12 v1@5842.34,3870.19 ; 5895.12,4363.6 J11.MP1@5895.12,4422.02 ; R180.1@6165.19,3800.17 6183.19,3818.17 v1(6184.15,3818.17) ; v1(6172.42,3724.14) 6176.54,3724.14 6185.59,3733.19 C114.1@6185.59,3747.34 ; C119.2@6308.91,3919.22 6325.92,3919.22 6331.6,3913.54 6331.6,3912.93 6345.47,3912.93 v1(6351.81,3906.59) ; R29.1@6595.21,3965.94 6595.21,3940.34 R24.1@6598.09,3937.46 6598.09,3863.56 U19.9@6611.18,3850.46 ; U19.9@6630.43,3888.85 U19.5@6668.27,3888.85 ; C129.2@6719.58,3803.87 6719.58,3791.85 v1(6726.69,3784.74) ; v1(6861.81,4003) 6861.81,4001.72 6872.94,3990.59 C5.2@6872.94,3977 6872.94,3955.87 6882.18,3946.63 U4.2@6882.18,3905.76 ; C70.2@3876,4337 C70.2@3876,4339.08
  Bottom Layer w15: C85.2@4020.26,4409.33 4020.26,4420.35 v1(4024.98,4425.07)
  other v1: 6274.82,3701.53 6952.41,3720.9 6573.56,3730.29 5170.1,3758.57 6598.2,3813.91 6641.68,3813.91 5842.34,3819.07 6621.18,3850.46 3347.03,3859.8 3264.38,3864.55 2681.88,3874.1 2707.59,3876.19 3556.71,3876.99 3595.28,3877.73 6598.73,3884.93 6639.57,3888.2 3263.43,3899.41 6260.55,3899.46 3349.12,3899.83 2681.87,3902.19 2707.36,3903.54 3662.07,3925.28 2939.63,3937.23 5553.54,3936.9 5842.34,3937.18 2938.52,3961.69 4419.27,3961.6 3680.37,3972.46 2967.71,3977.05 2992.16,3978.16 4419.27,3979.67 5842.34,3996.23 4419.21,3997.72 3956.48,4026.61 4006.48,4026.61 4056.48,4026.61 4106.48,4026.61 4450.49,4029.21 4468.83,4029.2 4486.89,4029.2 4504.94,4029.26 5842.34,4055.29 3956.48,4066.61 4006.48,4066.61 4056.48,4066.61 4106.48,4066.61 4156.48,4066.61 6548.66,4074.88 3634.65,4086.8 5012.07,4091.76 3956.48,4101.61 4006.48,4101.61 4056.48,4101.61 4106.48,4101.61 4156.48,4101.61 5842.34,4114.34 3297.94,4125.29 3318.19,4126.91 2861.28,4129.19 2886.83,4129.28 2940,4130.11 3270.82,4130.11 2957.52,4135 4419.8,4136 4006.48,4136.61 4056.48,4136.61 4106.48,4136.61 4156.48,4136.61 3255.99,4142.41 3290,4141.67 3370.14,4142.47 3397.17,4143.43 3453.72,4143.43 3483.39,4146.19 2928.4,4146.64 2910,4150.98 2947.97,4150.72 3274,4153.05 3318.19,4154.05 5061.86,4156.99 2886.83,4157.62 3298.46,4158.16 4953.59,4159.64 6533.31,4160.3 3698.53,4160.53 5842.34,4173.4 3956.48,4176.61 4006.48,4176.61 4056.48,4176.61 4106.48,4176.61 4156.48,4176.61 6887.81,4211 4006.48,4216.61 4056.48,4216.61 4106.48,4216.61 4156.48,4216.61 5111.53,4230.64 6477.81,4248.79 4944,4257.53 3708.13,4263.57 4450.55,4269.58 4468.6,4269.63 4486.66,4269.63 4505,4269.63 6487.81,4281 6559.81,4296 6519.81,4297.07 4419.28,4301.68 6388.81,4303 6725.81,4306 2957.65,4313.95 4419.28,4320.01 3036.36,4321.8 2957.56,4335.28 4419.28,4338.08 3036.27,4343.13 6566.81,4345 6494.81,4351.83 4419.22,4356.13 4024.98,4362.08 6387.81,4366 6512.81,4370 3281.16,4378.07 4450.5,4387.61 4468.84,4387.61 4486.9,4387.61 4504.95,4387.61 6493.81,4394.36 6387.81,4408 3281.55,4414.75 6514.81,4418 6372.91,4426 3303.56,4428.01 3327.17,4428.52 3604.82,4433.3 3579.88,4434.76 6388.68,4440 6493.81,4443.5 6539.81,4443.5 6591.81,4445 6516.81,4466 6389.55,4472 5458.19,4488.18 5507.38,4488.18 6493.81,4492.65 6528.81,4501.37 6571.81,4502.89 6390.42,4504 6469.81,4515.56 6547.81,4517.37 6492.17,4520.47 6696.81,4524.37 6943.81,4524.37 6517.09,4524.83 6642.81,4524.83 6746.64,4524.83 6781.79,4524.83 6591.83,4525.52 6414.36,4529.3 6392.81,4544.21 6527.94,4546.17 6553.74,4546.16 6579.54,4546.16 6605.34,4546.16 6631.14,4546.16 6656.94,4546.16 6682.74,4546.16 6708.54,4546.16 6734.34,4546.16 6760.15,4546.16 6785.95,4546.16 6811.75,4546.15 6837.55,4546.15 6863.35,4546.15 6889.15,4546.15 6914.95,4546.15 6940.75,4546.15 6514.43,4560.48 6540.23,4560.48 6566.03,4560.48 6591.83,4560.48 6617.64,4560.47 6643.44,4560.47 6669.24,4560.47 6695.04,4560.47 6720.84,4560.47 6746.64,4560.47 6772.44,4560.47 6798.24,4560.47 6824.04,4560.47 6849.84,4560.47 6875.65,4560.46 6901.45,4560.46 6927.25,4560.46 6407.43,4561.08 6396.81,4580.37 6414.7,4588.53 6436.24,4611.91 6410.81,4614.37 6375.72,4616.37 6962.81,4618.37 6466.94,4618.59 6486.08,4618.57 6505.22,4618.56 6530.23,4619.19 6556.03,4619.19 6581.83,4619.19 6607.64,4619.19 6633.44,4619.19 6659.24,4619.19 6685.04,4619.19 6710.84,4619.2 6736.64,4619.2 6762.44,4619.2 6788.24,4619.2 6814.04,4619.2 6839.84,4619.2 6865.65,4619.2 6891.45,4619.2 6917.25,4619.2 6943.05,4619.2
  other v2: 6621.18,3813.06 6799.78,3828.6 6598.54,3850.46 6643.82,3850.46 6778.13,3866 6821.43,3866 6621.18,3887.86 6799.78,3903.4 6293.77,4019.57 6343.38,4019.57 6392.99,4019.57 6251.84,4061.5 6293.77,4061.5 6343.38,4061.5 6392.99,4061.5 6434.91,4061.5 3107,4107.36 6251.84,4111.11 6293.77,4111.11 6343.38,4111.11 6392.99,4111.11 6251.84,4160.71 6293.77,4160.71 6343.38,4160.71 6392.99,4160.71 6293.77,4202.64 6343.38,4202.64 6392.99,4202.64 5923.44,4362.81 5923.44,4406.12
HD_AR_BSS_LOGGER: J2.43 RA2.7 | length 216.7
  Top Layer w5.5: v1(4559.93,4350.86) 4576.93,4350.86 4588.48,4362.41 RA2.7@4588.48,4413.17
  Bottom Layer w5.5: v1(4559.93,4350.86) 4559.93,4283.34 4570.82,4272.45 J2.43@4620.57,4272.45
HD_AR_CS1: J2.19 RA3.8 | length 314.3
  Top Layer w5.5: v1(4706.14,3859.2) 4706.14,3868.7 4722.1,3884.67 RA3.8@4749.31,3884.67
  Bottom Layer w5.5: J2.19@4620.57,4036.23 4685.35,4036.23 4711.7,4009.88 4711.7,3864.77 v1(4706.14,3859.2)
HD_AR_DMM_CLK: J2.10 R11.2 | length 93.9
  Bottom Layer w5.5: J2.10@4846.16,3937.81 4846.29,3937.94 R11.2@4940,3937.94
HD_AR_DMM_SYNC: J2.8 R10.2 | length 62.4
  Bottom Layer w5.5: J2.8@4846.16,3918.12 4846.16,3918.75 4904.75,3918.75 R10.2@4907,3921
HD_AR_DP0: J2.27 R88.2 | length 332.7
  Top Layer w5.5: v1(4706.93,4095.17) 4715.82,4086.28 4727.46,4086.28 4753.42,4060.33 4790.43,4060.33 4820.52,4090.42 4820.52,4153.84 4807.4,4166.97 R88.2@4807.4,4182.65
  Bottom Layer w5.5: J2.27@4620.57,4114.97 4671.25,4114.97 4675.76,4110.46 4691.64,4110.46 v1(4706.93,4095.17)
HD_AR_DP1: J2.29 R130.2 | length 310
  Top Layer w5.5: v1(4557.19,4143.31) 4605.78,4191.9 4605.78,4283.48 4617.95,4295.65 R130.2@4617.95,4361.13
  Bottom Layer w5.5: v1(4557.19,4143.31) 4565.84,4134.66 J2.29@4620.57,4134.66
HD_AR_DP2: J2.31 R132.2 | length 311.6
  Top Layer w5.5: v1(4708.21,4126.21) 4708.21,4122.45 4744.09,4086.57 4782.4,4086.57 4799.64,4103.81 4799.64,4155.27 4791.92,4162.99 4791.92,4163.13 4783.89,4171.15 4783.89,4182.5 R132.2@4783.74,4182.65
  Bottom Layer w5.5: J2.31@4620.57,4154.34 4696.66,4154.34 4708.21,4142.79 v1(4708.21,4126.21)
HD_AR_DP3: J2.33 R133.2 | length 140.6
  Top Layer w5.5: v1(4682.93,4176.03) 4682.93,4190.24 4720.33,4227.63 R133.2@4730.66,4227.63
  Bottom Layer w5.5: J2.33@4620.57,4174.03 4667.31,4174.03 4669.31,4176.03 v1(4682.93,4176.03)
HD_AR_DP4: J2.35 R135.2 | length 126
  Top Layer w5.5: v1(4705.93,4176.03) 4714.04,4184.13 R135.2@4714.04,4196.8
  Bottom Layer w5.5: J2.35@4620.57,4193.71 4621.21,4194.35 4698.76,4194.35 4705.93,4187.19 v1(4705.93,4176.03) v1@4705.93,4173.91
HD_AR_DP5: J2.37 R137.2 | length 582.1
  Top Layer w5.5: v1@4557.28,4174.75 4539.44,4156.91 4539.44,4097.34 4550.03,4086.75 4566.15,4086.75 4598.1,4054.8 4598.1,4039.08 4627.69,4009.49 4688.16,4009.49 4700.91,3996.73 4700.91,3953.29 4667.89,3920.26 4667.89,3880.45 4648.49,3861.06 4648.49,3827.6 R137.2@4649.26,3826.83
  Bottom Layer w5.5: v1(4558.03,4174) 4558.03,4198.13 4573.29,4213.4 J2.37@4620.57,4213.4
HD_AR_DP6: J2.39 R138.2 | length 158.1
  Top Layer w5.5: v1(4682.65,4241.56) 4703.85,4262.77 4720.85,4262.77 4742.55,4284.46 R138.2@4757.37,4284.46
  Bottom Layer w5.5: J2.39@4620.57,4233.08 4674.16,4233.08 v1(4682.65,4241.56)
HD_AR_DP7: J2.41 R140.2 | length 537.6
  Top Layer w5.5: v1(4557.19,4115.29) 4609.6,4062.88 4609.6,4043.84 4632.45,4020.99 4692.92,4020.99 4714.81,3999.1 4714.81,3934.7 R140.2@4683.56,3903.45
  Bottom Layer w5.5: v1(4557.19,4115.29) 4539.44,4133.04 4539.44,4229.07 4563.13,4252.77 J2.41@4620.57,4252.77
HD_AR_HOSTINTR1: J2.16 RA9.3 | length 96.7
  Bottom Layer w5.5: J2.16@4846.16,3996.86 4909.96,3996.86 4919.19,3987.64 RA9.3@4939.02,3987.64
HD_AR_MCUCLKOUT: J2.47 RA1.8 | length 304
  Top Layer w5.5: v1(4705.93,4292.02) 4714.77,4292.02 4726.28,4303.53 4726.28,4313.37 4756.21,4343.3 4756.21,4447.72 4756.3,4447.8 RA1.8@4756.3,4468.67
  Bottom Layer w5.5: J2.47@4620.57,4311.82 4699.4,4311.82 4705.93,4305.3 v1(4705.93,4292.02)
HD_AR_OSC_CLKOUT: J2.45 RA1.7 | length 274.3
  Top Layer w5.5: v1(4677.93,4292.14) 4677.93,4300.43 4691.13,4313.64 4710.28,4313.64 4744.5,4347.85 4744.5,4435.74 4740.55,4439.7 RA1.7@4740.55,4468.67
  Bottom Layer w5.5: J2.45@4620.57,4292.14 v1(4677.93,4292.14)
HD_AR_PMIC_CLKOUT_SOP2: J2.49 RA1.5 | length 216
  Top Layer w5.5: v1(4677.93,4334.51) 4721.5,4378.08 4721.5,4426.22 4711.5,4436.22 4711.5,4455.32 4709.05,4457.77 RA1.5@4709.05,4468.67
  Bottom Layer w5.5: J2.49@4620.57,4331.51 4623.57,4334.51 v1(4677.93,4334.51)
HD_AR_SCL: J2.55 RA2.5 | length 144.3
  Top Layer w5.5: v1(4539.66,4372.53) 4539.66,4388.23 4556.98,4405.56 RA2.5@4556.98,4413.17
  Bottom Layer w5.5: v1(4539.66,4372.53) 4539.66,4384.9 4546.38,4391.63 4619.5,4391.63 J2.55@4620.57,4390.56
HD_AR_SDA: J2.53 RA2.6 | length 101.8
  Top Layer w5.5: v1(4563.2,4373.88) 4563.2,4390.63 4572.73,4400.16 RA2.6@4572.73,4413.17
  Bottom Layer w5.5: v1(4563.2,4373.88) 4566.2,4370.88 J2.53@4620.57,4370.88
HD_AR_TCK: J2.15 RA4.7 | length 164.6
  Top Layer w5.5: v1(4552.59,4003.26) 4569.09,4003.26 4576.29,4010.46 4592.85,4010.46 4613.18,3990.14 4613.18,3968.8 RA4.7@4612.69,3968.32
  Bottom Layer w5.5: v1(4552.59,4003.26) 4558.99,3996.86 J2.15@4620.57,3996.86
HD_AR_TDI: J2.11 RA4.5 | length 102.8
  Top Layer w5.5: RA4.5@4644.19,3968.32 4678.62,3968.32 v1(4681.54,3965.4)
  Bottom Layer w5.5: J2.11@4620.57,3957.49 4673.64,3957.49 v1(4681.54,3965.4)
HD_AR_TDO_SOP0: J2.17 RA4.6 | length 155.4
  Top Layer w5.5: RA4.6@4628.44,3968.32 4628.44,3984.53 4633.29,3989.38 v1(4683.16,3989.38)
  Bottom Layer w5.5: J2.17@4620.57,4016.55 4670.75,4016.55 4683.16,4004.13 v1(4683.16,3989.38)
HD_AR_TMS: J2.13 RA4.8 | length 146.7
  Top Layer w5.5: v1(4551.95,3978.41) 4559.05,3985.51 4573.47,3985.51 4585.23,3997.26 4589.79,3997.26 4596.94,3990.11 RA4.8@4596.94,3968.32
  Bottom Layer w5.5: v1(4551.95,3978.41) 4619.34,3978.41 J2.13@4620.57,3977.18
HD_AR_WARMRST: J2.51 RA1.6 | length 251.7
  Top Layer w5.5: v1(4705.93,4334.39) 4733,4361.46 4733,4430.98 4724.8,4439.18 RA1.6@4724.8,4468.67
  Bottom Layer w5.5: J2.51@4620.57,4351.19 4666.81,4351.19 4672.24,4356.63 4693.97,4356.63 4705.93,4344.67 v1(4705.93,4334.39)
HD_SPI_CLK1: J2.21 RA3.7 | length 396.4
  Top Layer w5.5: v1(4679.93,4055.92) 4668.47,4067.38 4628.14,4067.38 4621.38,4060.62 4621.38,4048.32 4637.22,4032.49 4697.69,4032.49 4733.08,3997.1 4733.08,3926.57 4765.06,3894.59 RA3.7@4765.06,3884.67
  Bottom Layer w5.5: J2.21@4620.57,4055.92 v1(4679.93,4055.92)
HD_SPI_MISO1: J2.25 RA3.5 | length 325.8
  Top Layer w5.5: v1(4683.12,4092.71) 4701.05,4074.78 4713.3,4074.78 4756.08,4032.01 4756.08,3936.1 4796.56,3895.62 RA3.5@4796.56,3884.67
  Bottom Layer w5.5: J2.25@4620.57,4095.29 4623.14,4092.71 v1(4683.12,4092.71)
HD_SPI_MOSI1: J2.23 RA3.6 | length 295.7
  Top Layer w5.5: v1(4705.93,4055.8) 4744.58,4017.15 4744.58,3931.34 4780.81,3895.1 RA3.6@4780.81,3884.67
  Bottom Layer w5.5: J2.23@4620.57,4075.6 4670.79,4075.6 4672.47,4073.92 4687.81,4073.92 v1(4705.93,4055.8)
INTN: R95.1 TP46.1 U10.11 | length 116.7
  Bottom Layer w5.5: TP46.1@5169.8,4471.3 5229.81,4471.3 5234.01,4467.11 R95.1@5234.01,4457.6 U10.11@5275.3,4457.6
JTAG_TCK: J7.8 U8.25 | length 633.7
  Top Layer w5.5: v1(6196.43,3977.5) 6234.86,3977.5 U8.25@6235.11,3977.25
  Sig2 w4.2: J7.8@6183.84,4515.56 6189.79,4515.56 6254.56,4450.79 6254.56,4387.9 6222.04,4355.38 6222.04,4212.05 6207,4197.01 6207,3988.07 v1(6196.43,3977.5)
JTAG_TDI: J7.4 R113.1 U8.27 | length 1924.5
  Top Layer w5.5: U8.27@6274.48,3977.25 6274.48,3958.37 v1(6286.18,3946.67)
  Sig1 w4.2: v1(5177.22,4403.8) 5196.55,4384.47 5375.07,4384.47 5458.16,4467.56 5835.37,4467.56 5912.96,4389.97 6025.26,4389.97 6119.7,4484.41 6252.69,4484.41 J7.4@6283.84,4515.56
  Sig2 w4.2: J7.4@6283.84,4515.56 6272.87,4504.59 6272.87,4378.37 6243.5,4349 6243.5,4201.11 6226,4183.61 6226,4006.85 v1(6286.18,3946.67)
  Bottom Layer w5.5: v1(5177.22,4403.8) 5182.02,4399 R113.1@5213.29,4399
JTAG_TDO: J7.6 U8.26 | length 640.6
  Top Layer w5.5: v1(6249.18,3949.46) 6254.8,3955.08 U8.26@6254.8,3977.25
  Sig2 w4.2: J7.6@6233.84,4515.56 6262.96,4486.43 6262.96,4384.42 6233.16,4354.61 6233.16,4207.87 6217,4191.72 6217,3981.65 v1(6249.18,3949.46)
JTAG_TMS: J7.10 U8.24 | length 631.3
  Top Layer w5.5: v1(6185.59,4002.46) 6185.78,4002.65 6209.33,4002.65 U8.24@6209.52,4002.84
  Sig2 w4.2: J7.10@6133.84,4515.56 6171.82,4477.58 6215.89,4477.58 6241.98,4451.49 6241.98,4387.19 6208.49,4353.7 6208.26,4353.7 6208.26,4211.69 6196,4199.44 6196,4012.87 v1(6185.59,4002.46)
MRDY: TP16.1 U8.21 | length 81.4
  Top Layer w5.5: TP16.1@6141.18,4093.46 6155.18,4093.46 6186.75,4061.9 U8.21@6209.52,4061.9
NetA1_4: A1.4 C99.1 C104.1 | length 143.8
  Top Layer w14.15: C99.1@6860.47,4589.83 6942.22,4589.83 A1.4@7004.3,4589.83
NetC8_1: C8.1 U4.4 | length 99.9
  Bottom Layer w5.5: C8.1@6913.21,3719.01 6926.82,3719.01 6932.56,3724.75 6932.56,3759.35 6919.58,3772.33 U4.4@6919.58,3797.49
NetC13_2: C13.2 U7.9 | length 46.9
  Bottom Layer w5.5: C13.2@5252.95,4010.48 5252.95,3989.51 5265.35,3977.1 U7.9@5265.35,3968.74
NetC21_2: C21.2 L1.2 | length 34.8
  Top Layer w14.15: L1.2@6505.92,4324.41 C21.2@6540.73,4324.41
NetC22_1: C22.1 L6.2 L9.1 | length 203.8
  Top Layer w14.15: L6.2@6415.18,4415.16 6415.18,4479.36 L9.1@6441.85,4506.02 6468.51,4479.36 C22.1@6468.51,4415.16
NetC24_1: C24.1 U8.23 | length 65.2
  Top Layer w5.5: C24.1@6152.19,4003.46 6154.14,4003.46 6173.2,4022.52 U8.23@6209.52,4022.52
NetC41_1: C41.1 L9.2 L10.1 | length 168.6
  Top Layer w14.15: L9.2@6441.85,4543.42 6441.85,4554.87 cw(c6476.81,4554.87) 6476.81,4589.83 C41.1@6487.09,4589.83 L10.1@6579.09,4589.83
NetC43_2: C43.2 FL12.1 U12.3 | length 71.5
  Top Layer w10: C43.2@5901.79,4292.07 5901.96,4292.24 5936.06,4292.24 FL12.1@5936.23,4292.41 U12.3@5936.23,4329.34
NetC93_1: C93.1 C99.2 | length 83.6
  Top Layer w14.15: C93.1@6737.47,4589.83 C99.2@6821.1,4589.83
NetC93_2: C93.2 L10.2 | length 81.6
  Top Layer w14.15: L10.2@6616.49,4589.83 C93.2@6698.1,4589.83
NetC106_2: C106.2 R119.1 R126.2 | length 350.7
  Top Layer w10: v1(5832.42,4512.62) 5832.96,4513.16 5843.92,4513.16 5864.3,4492.77 R119.1@5866.27,4492.77 ; R126.2@5980.6,4492.48 5980.84,4492.25 6042.09,4492.25 C106.2@6042.33,4492.01 6042.33,4524.71 v1@6041.47,4525.56
  Sig2 w10: v1(5832.42,4512.62) 5840.37,4520.56 v1(6041.47,4520.56)
NetC108_2: C108.2 FL3.1 U17.3 | length 78.4
  Top Layer w10: FL3.1@6667.81,3855.69 FL3.1@6668.13,3856 ; FL3.1@6670.79,3848.88 6684.78,3848.88 6691.9,3856 C108.2@6709.78,3856 6719.78,3856 6722.58,3853.2 U17.3@6744.66,3853.2
NetC110_2: C110.2 R114.1 R117.2 | length 224.3
  Top Layer w4: R114.1@6909.57,3928.98 6910.6,3930 v1(6944.81,3930) ; R117.2@6909.66,3803.83 6917.51,3795.99 6949.12,3795.99 C110.2@6951.81,3793.3 ; v1(6947.13,3826.69) 6952.51,3821.3 6952.51,3794 C110.2@6951.81,3793.3 ; C110.2@6951.81,3795.27 C110.2@6951.81,3793.3
  Sig2 w4.2: v1(6944.81,3930) 6944.81,3829 v1(6947.13,3826.69)
NetD1_2: D1.2 FL2.2
NetD2_2: D2.2 FL11.2
NetFL4_1: FL4.1 J11.1 J11.2 J11.3
NetJ2_12: J2.12 RA9.1 | length 93.4
  Bottom Layer w5.5: J2.12@4846.16,3957.49 4914.14,3957.49 4915.49,3956.14 RA9.1@4939.02,3956.14
NetJ2_14: J2.14 RA9.2 | length 95.1
  Bottom Layer w5.5: J2.14@4846.16,3977.18 4913.28,3977.18 4918.58,3971.89 RA9.2@4939.02,3971.89
NetJ2_18: J2.18 RA9.4 | length 98.3
  Bottom Layer w5.5: J2.18@4846.16,4016.55 4917.47,4016.55 4930.63,4003.38 RA9.4@4939.02,4003.38
NetJ2_22: J2.22 RA8.1 | length 91.6
  Bottom Layer w5.5: J2.22@4846.16,4055.92 4903.41,4055.92 4919.74,4072.25 RA8.1@4931.04,4072.25
NetJ2_24: J2.24 RA8.2 | length 90
  Bottom Layer w5.5: J2.24@4846.16,4075.6 4899.11,4075.6 4911.5,4088 RA8.2@4931.04,4088
NetJ2_28: J2.28 RA8.3 | length 91.9
  Bottom Layer w4: J2.28@4846.16,4114.97 4849.05,4117.87 4900.55,4117.87 4913.13,4105.29 4929.5,4105.29 RA8.3@4931.04,4103.74
NetJ2_30: J2.30 RA8.4 | length 93.8
  Bottom Layer w4: J2.30@4846.16,4134.66 4886.03,4134.66 4891.82,4128.87 4905.1,4128.87 4917.68,4116.29 4927.83,4116.29 RA8.4@4931.04,4119.49
NetJ2_34: J2.34 RA7.1 | length 94.1
  Bottom Layer w4: J2.34@4846.16,4174.03 4892.84,4174.03 4897.18,4178.37 4906.52,4178.37 4920.55,4192.4 4929.32,4192.4 RA7.1@4931.69,4190.03
NetJ2_36: J2.36 RA7.2 | length 94.1
  Bottom Layer w4: J2.36@4846.16,4193.71 4892.84,4193.71 4897.18,4189.37 4901.96,4189.37 4916,4203.4 4929.32,4203.4 RA7.2@4931.69,4205.78
NetJ2_40: J2.40 RA7.3 | length 93.3
  Bottom Layer w4: J2.40@4846.16,4233.08 4892.84,4233.08 4896.4,4236.64 4909.94,4236.64 4919.3,4227.27 4923.48,4227.27 4929.23,4221.53 RA7.3@4931.69,4221.53
NetJ2_42: J2.42 RA7.4 | length 92
  Bottom Layer w4: J2.42@4846.16,4252.77 4892.84,4252.77 4898.97,4246.64 4915.49,4246.64 4924.86,4237.27 RA7.4@4931.69,4237.27
NetJ2_46: J2.46 RA6.1 | length 90.9
  Bottom Layer w4: J2.46@4846.16,4292.14 4892.84,4292.14 4897.18,4296.48 4904.46,4296.48 4914.12,4306.15 4919.89,4306.15 4922.26,4303.77 RA6.1@4930.26,4303.77
NetJ2_48: J2.48 RA6.2 | length 90.9
  Bottom Layer w4: J2.48@4846.16,4311.82 4892.84,4311.82 4897.18,4307.48 4899.9,4307.48 4903.44,4311.02 4909.57,4317.15 4919.89,4317.15 4922.26,4319.52 RA6.2@4930.26,4319.52
NetJ2_52: J2.52 RA6.3 | length 90.7
  Bottom Layer w5.5: J2.52@4846.16,4351.19 4897.66,4351.19 4913.58,4335.27 RA6.3@4930.26,4335.27
NetJ2_54: J2.54 RA6.4 | length 92.3
  Bottom Layer w5.5: J2.54@4846.16,4370.88 4899.09,4370.88 4918.95,4351.02 RA6.4@4930.26,4351.02
NetJ2_56: J2.56 RA5.1 | length 92.2
  Bottom Layer w5.5: J2.56@4846.16,4390.56 4899.25,4390.56 4917.78,4409.09 RA5.1@4930.68,4409.09
NetJ2_57: J2.57 R14.1 | length 428.2
  Top Layer w5.5: v1(4831,4471.63) 4831,4488.23 4836.24,4493.46 R14.1@4886,4493.46
  Bottom Layer w5.5: J2.57@4620.57,4410.25 4669.54,4410.25 4678.95,4400.84 4693.94,4400.84 4711.09,4417.99 4711.09,4516 4723.3,4528.21 4785.55,4528.21 4831,4482.76 v1(4831,4471.63)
